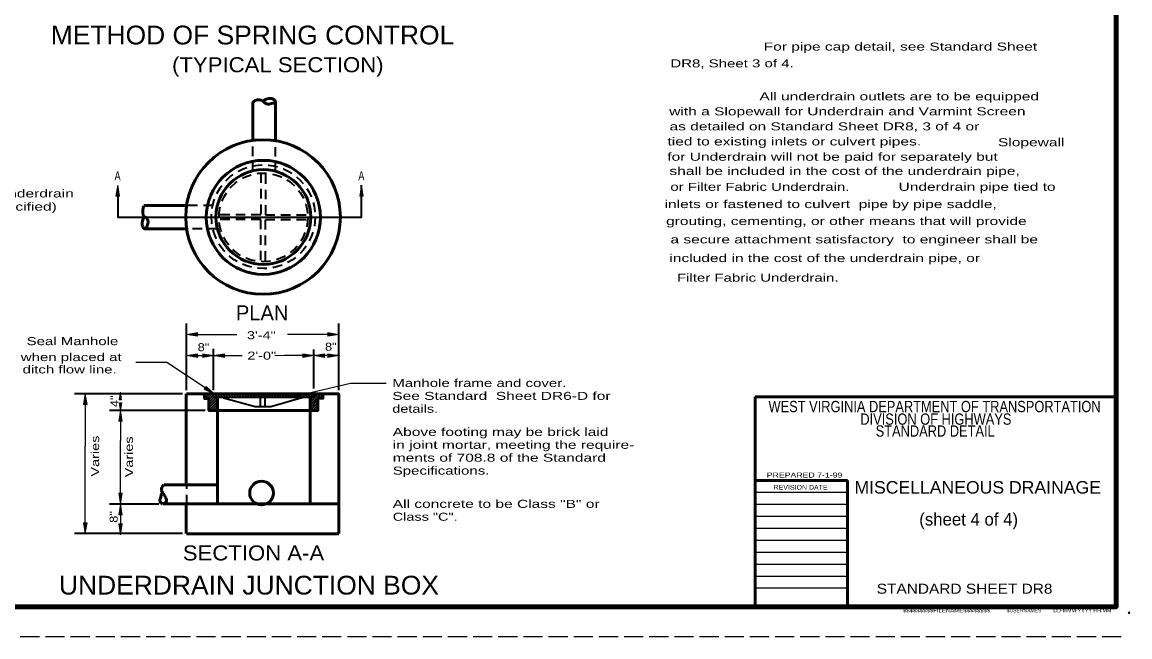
# Model space of a CAD drawing. Extents: x 36 to 71.3, y 0.3 to 22.3.
# Drawn here: x 52.91 to 71.32, y 0.32 to 10.54 of the extents above; entities that cross this region are included whole.
import ezdxf
from ezdxf.enums import TextEntityAlignment as Align

# ---------------------------------------------------------------- set-up
doc = ezdxf.new("R2010")
doc.units = 0
doc.header["$LTSCALE"] = 0.053
doc.header["$PDMODE"] = 32
doc.header["$PDSIZE"] = 0.0265
doc.linetypes.add('LONG_DASHED', pattern=[7.5, 6, -1.5])
doc.linetypes.add('MEDIUM_DASHED', pattern=[4.5, 3, -1.5])
for name, color, linetype, lineweight in [('1', 7, 'Continuous', 13), ('2', 7, 'Continuous', 13), ('3', 7, 'MEDIUM_DASHED', 53), ('4', 7, 'Continuous', 13)]:
    doc.layers.add(name, color=color, linetype=linetype, lineweight=lineweight)

msp = doc.modelspace()

# ---------------------------------------------------------------- hatches: boundary and pattern name
at = {"layer": '1'}
for points in [[(55.82417, 5.38142), (55.82417, 5.32142), (55.64417, 5.35142), (55.64417, 5.35142)], [(57.99158, 5.38142), (57.99158, 5.32142), (58.17158, 5.35142), (58.17158, 5.35142)], [(53.932, 4.18375), (53.992, 4.18375), (53.962, 4.36375), (53.962, 4.36375)], [(54.52358, 4.26292), (54.56558, 4.26292), (54.54458, 4.38892), (54.54458, 4.38892)], [(54.51642, 3.90858), (54.57642, 3.90858), (54.54642, 4.08858), (54.54642, 4.08858)], [(54.52542, 4.21458), (54.56733, 4.21458), (54.54642, 4.08858), (54.54642, 4.08858)], [(54.51642, 2.71217), (54.57642, 2.71217), (54.54642, 2.53217), (54.54642, 2.53217)], [(54.51642, 2.35217), (54.57642, 2.35217), (54.54642, 2.53217), (54.54642, 2.53217)], [(53.932, 2.22217), (53.992, 2.22217), (53.962, 2.04217), (53.962, 2.04217)], [(54.51642, 2.20217), (54.57642, 2.20217), (54.54642, 2.02225), (54.54642, 2.02225)]]:
    msp.add_hatch(color=256, dxfattribs=at).paths.add_polyline_path(points)
at = {"layer": '2'}
for points in [[(54.47033, 7.65), (54.53033, 7.65), (54.50033, 7.83), (54.50033, 7.83)], [(58.52092, 7.65), (58.58092, 7.65), (58.55092, 7.83), (58.55092, 7.83)], [(55.82417, 4.96867), (55.82417, 5.02867), (55.64417, 4.99867), (55.64417, 4.99867)], [(55.91408, 4.96867), (55.91408, 5.02867), (56.09408, 4.99867), (56.09408, 4.99867)], [(56.27417, 4.96867), (56.27417, 5.02867), (56.09408, 4.99867), (56.09408, 4.99867)], [(57.57775, 4.96867), (57.57775, 5.02867), (57.75775, 4.99867), (57.75775, 4.99867)], [(57.93775, 4.96867), (57.93775, 5.02867), (57.75775, 4.99867), (57.75775, 4.99867)], [(57.99158, 5.02867), (57.99158, 4.96867), (58.17158, 4.99867), (58.17158, 4.99867)], [(55.96925, 4.48833), (55.93608, 4.43833), (56.10258, 4.36375), (56.10258, 4.36375)], [(57.55025, 4.31875), (57.53642, 4.37708), (57.36817, 4.30642), (57.36817, 4.30642)]]:
    msp.add_hatch(color=256, dxfattribs=at).paths.add_polyline_path(points)

# ---------------------------------------------------------------- linework, layer by layer
at = {"layer": '1', "lineweight": 53}
for p, q in [((56.74692, 8.55658), (56.74692, 9.18117)), ((57.119, 8.55658), (57.119, 9.19325)), ((55.66483, 7.49225), (54.93608, 7.49225)), ((55.65717, 7.10817), (54.96808, 7.10817)), ((55.63758, 4.36375), (55.63758, 2.84675)), ((56.15717, 4.30325), (56.15717, 2.53683)), ((57.69492, 4.30325), (57.69492, 2.53683)), ((71.08992, 4.31392), (65.08992, 4.31392)), ((65.08992, 0.82408), (65.08992, 4.31392)), ((71.08992, 0.82408), (71.08992, 3.32308)), ((56.16042, 2.8515), (55.27317, 2.8515)), ((66.62783, 2.92308), (65.08992, 2.92308)), ((66.62783, 0.82408), (66.62783, 2.92308)), ((55.63533, 2.53683), (55.25342, 2.53683)), ((55.63758, 2.526), (55.63758, 2.04217)), ((55.64417, 2.53758), (58.17158, 2.53758)), ((65.08992, 2.23408), (65.08992, 0.82408)), ((55.64417, 2.0365), (58.17158, 2.0365)), ((71.08992, 0.82408), (65.08992, 0.82408))]:
    msp.add_line(p, q, dxfattribs=at)
at = {"layer": '1', "lineweight": 35}
for p, q in [((55.64417, 4.42625), (55.64417, 5.53142)), ((58.17158, 4.42625), (58.17158, 5.53142)), ((55.57508, 4.36375), (53.782, 4.36375)), ((55.9425, 4.32458), (55.98158, 4.36375)), ((55.9475, 4.2855), (56.02575, 4.36375)), ((55.99167, 4.2855), (56.07, 4.36375)), ((56.01625, 4.26583), (56.09108, 4.34067)), ((56.01625, 4.17742), (56.14525, 4.30642)), ((56.01625, 4.22158), (56.10108, 4.30642)), ((56.01625, 4.13325), (56.15717, 4.27408)), ((56.11417, 4.30642), (56.05692, 4.36375)), ((56.15833, 4.30642), (56.10108, 4.36375)), ((56.20258, 4.30642), (56.14525, 4.36375)), ((56.24675, 4.30642), (56.1895, 4.36375)), ((56.29092, 4.30642), (56.23367, 4.36375)), ((56.33517, 4.30642), (56.27783, 4.36375)), ((56.37933, 4.30642), (56.32208, 4.36375)), ((56.4235, 4.30642), (56.36625, 4.36375)), ((56.46775, 4.30642), (56.41042, 4.36375)), ((56.51192, 4.30642), (56.45467, 4.36375)), ((56.55608, 4.30642), (56.49883, 4.36375)), ((56.60033, 4.30642), (56.543, 4.36375)), ((56.6445, 4.30642), (56.58725, 4.36375)), ((56.68867, 4.30642), (56.63142, 4.36375)), ((56.73292, 4.30642), (56.67558, 4.36375)), ((56.77708, 4.30642), (56.71983, 4.36375)), ((56.82125, 4.30642), (56.764, 4.36375)), ((56.8655, 4.30642), (56.80817, 4.36375)), ((56.90967, 4.30642), (56.85242, 4.36375)), ((56.86825, 4.30642), (56.86825, 4.15392)), ((56.95383, 4.30642), (56.89658, 4.36375)), ((56.99808, 4.30642), (56.94075, 4.36375)), ((56.94533, 4.30642), (56.94533, 4.15392)), ((57.04225, 4.30642), (56.985, 4.36375)), ((57.08642, 4.30642), (57.02917, 4.36375)), ((57.13067, 4.30642), (57.07333, 4.36375)), ((57.17483, 4.30642), (57.11758, 4.36375)), ((57.219, 4.30642), (57.16175, 4.36375)), ((57.26325, 4.30642), (57.20592, 4.36375)), ((57.30742, 4.30642), (57.25017, 4.36375)), ((57.35158, 4.30642), (57.29433, 4.36375)), ((57.39583, 4.30642), (57.3385, 4.36375)), ((57.44, 4.30642), (57.38275, 4.36375)), ((57.48417, 4.30642), (57.42692, 4.36375)), ((57.52842, 4.30642), (57.47108, 4.36375)), ((57.57258, 4.30642), (57.51533, 4.36375)), ((57.61675, 4.30642), (57.5595, 4.36375)), ((57.661, 4.30642), (57.60367, 4.36375)), ((57.70517, 4.30642), (57.64792, 4.36375)), ((57.74933, 4.30642), (57.69208, 4.36375)), ((57.69492, 4.22092), (57.83775, 4.36375)), ((57.69492, 4.17675), (57.88192, 4.36375)), ((57.69492, 4.26517), (57.73625, 4.30642)), ((57.69492, 4.13258), (57.82592, 4.26358)), ((57.75658, 4.34342), (57.73625, 4.36375)), ((57.75658, 4.32675), (57.79358, 4.36375)), ((57.75658, 4.36133), (57.75658, 4.30642)), ((57.85267, 4.29033), (57.90958, 4.34717)), ((55.95375, 4.08858), (54.36642, 4.08858)), ((56.01625, 4.089), (56.15717, 4.22992)), ((56.06, 4.08858), (56.15717, 4.18575)), ((56.10417, 4.08858), (56.15717, 4.1415)), ((56.14833, 4.08858), (56.15717, 4.09733)), ((57.69517, 4.08858), (57.82592, 4.21933)), ((57.73933, 4.08858), (57.82592, 4.17517)), ((57.78358, 4.08858), (57.82592, 4.131)), ((55.18517, 2.53217), (54.36642, 2.53217)), ((55.57508, 2.04217), (53.782, 2.04217))]:
    msp.add_line(p, q, dxfattribs=at)
at = {"layer": '1', "lineweight": 25}
for p, q in [((55.82417, 5.35142), (56.47733, 5.35142)), ((57.99158, 5.35142), (57.32058, 5.35142)), ((53.962, 4.18375), (53.962, 3.49442)), ((54.54642, 3.90858), (54.54642, 3.58683)), ((54.54642, 2.71217), (54.54642, 3.58683)), ((53.962, 2.22217), (53.962, 3.49442)), ((66.62783, 2.72308), (65.08992, 2.72308)), ((66.62783, 2.52408), (65.08992, 2.52408)), ((54.54642, 2.35217), (54.54642, 2.06542)), ((66.62783, 2.32508), (65.08992, 2.32508)), ((66.62783, 2.12608), (65.08992, 2.12608)), ((66.62783, 1.92708), (65.08992, 1.92708)), ((66.62783, 1.72808), (65.08992, 1.72808)), ((66.62783, 1.52908), (65.08992, 1.52908)), ((66.62783, 1.33008), (65.08992, 1.33008)), ((66.62783, 1.13108), (65.08992, 1.13108))]:
    msp.add_line(p, q, dxfattribs=at)
at = {"layer": '1'}
msp.add_line((55.93742, 4.36375), (55.9425, 4.36883), dxfattribs=at)
at = {"layer": '1', "linetype": 'LONG_DASHED', "lineweight": 25}
msp.add_line((71.17325, 0.32408), (35.97325, 0.32408), dxfattribs=at)
at = {"layer": '1', "lineweight": 158}
msp.add_lwpolyline([(71.08992, 21.82408), (71.08992, 0.82408), (38.58992, 0.82408)], dxfattribs=at)
at = {"layer": '1'}
for points in [[(55.82417, 5.38142), (55.82417, 5.32142), (55.64417, 5.35142), (55.64417, 5.35142)], [(57.99158, 5.38142), (57.99158, 5.32142), (58.17158, 5.35142), (58.17158, 5.35142)], [(53.932, 4.18375), (53.992, 4.18375), (53.962, 4.36375), (53.962, 4.36375)], [(54.52358, 4.26292), (54.56558, 4.26292), (54.54458, 4.38892), (54.54458, 4.38892)], [(54.51642, 3.90858), (54.57642, 3.90858), (54.54642, 4.08858), (54.54642, 4.08858)], [(54.52542, 4.21458), (54.56733, 4.21458), (54.54642, 4.08858), (54.54642, 4.08858)], [(54.51642, 2.71217), (54.57642, 2.71217), (54.54642, 2.53217), (54.54642, 2.53217)], [(54.51642, 2.35217), (54.57642, 2.35217), (54.54642, 2.53217), (54.54642, 2.53217)], [(53.932, 2.22217), (53.992, 2.22217), (53.962, 2.04217), (53.962, 2.04217)], [(54.51642, 2.20217), (54.57642, 2.20217), (54.54642, 2.02225), (54.54642, 2.02225)]]:
    msp.add_lwpolyline(points, close=True, dxfattribs=at)
at = {"layer": '1', "lineweight": 53}
for points in [[(55.64417, 4.36375), (58.17158, 4.36375), (58.17158, 2.04217)], [(55.9425, 4.37342), (55.9425, 4.2855), (56.01625, 4.2855), (56.01625, 4.08858), (57.82592, 4.08858), (57.82592, 4.29033), (57.90958, 4.29033), (57.90958, 4.36375)]]:
    msp.add_lwpolyline(points, dxfattribs=at)
at = {"layer": '1', "lineweight": 35}
for points in [[(56.09108, 4.36133), (56.09108, 4.30642), (57.75658, 4.30642)], [(56.25508, 4.29917), (56.78242, 4.1515), (57.04433, 4.1515), (57.58375, 4.30642)]]:
    msp.add_lwpolyline(points, dxfattribs=at)
at = {"layer": '1', "lineweight": 53}
for centre, radius in [((56.91425, 7.30258), 1.28466), ((56.91975, 7.29692), 0.94816), ((56.91975, 7.30258), 0.78758), ((56.88975, 2.71475), 0.19625)]:
    msp.add_circle(centre, radius, dxfattribs=at)
for centre, radius, start, end in [((56.83833, 9.16983), 0.0961, 155.2019, 175.63882), ((56.79783, 9.1885), 0.05149, 127.0797, 155.12247), ((56.84, 9.133), 0.1212, 108.94125, 127.18911), ((56.83275, 9.15408), 0.09893, 88.71588, 108.94361), ((56.83058, 9.055), 0.19807, 76.71641, 88.71898), ((56.85317, 9.1515), 0.09893, 59.59849, 76.61699), ((56.8565, 9.15658), 0.09284, 40.84841, 59.78068), ((57.05033, 9.09525), 0.1881, 128.71883, 134.42111), ((56.99975, 9.28008), 0.09628, 220.69947, 239.29641), ((56.98325, 9.1785), 0.08118, 119.88486, 128.57223), ((57.02867, 9.10025), 0.17164, 109.56978, 120.00186), ((57.07258, 8.9765), 0.30301, 101.70708, 109.55079), ((57.03217, 9.17083), 0.10452, 78.59323, 101.63549), ((57.03208, 9.16967), 0.10561, 55.75148, 78.65852), ((57.042, 9.18442), 0.08784, 22.54048, 55.73033), ((57.11183, 9.21333), 0.01232, 283.06396, 22.6714), ((57.06933, 9.39767), 0.23291, 239.34105, 250.23371), ((57.00117, 9.208), 0.03134, 250.28519, 280.2853), ((56.95392, 9.46933), 0.29692, 280.25658, 284.97067), ((57.29667, 8.18033), 1.03686, 102.34271, 104.8682), ((57.21133, 8.58275), 0.62555, 100.5317, 102.58856), ((57.026, 9.591), 0.39957, 280.23196, 282.80535), ((55.21508, 7.39042), 0.29891, 176.13604, 181.98558), ((55.0645, 7.385), 0.14822, 181.89394, 194.28181), ((55.27492, 7.38525), 0.35896, 170.60889, 175.95477), ((54.99908, 7.43108), 0.07936, 159.14959, 170.75763), ((55.13867, 7.37817), 0.22868, 152.37523, 159.20126), ((55.11692, 7.19258), 0.21035, 167.07021, 180.02724), ((55.03525, 7.19242), 0.12864, 179.95854, 196.55623), ((55.0305, 7.21258), 0.12168, 152.26599, 167.11937), ((55.05458, 7.38258), 0.13805, 194.32618, 207.14842), ((55.07525, 7.1885), 0.17248, 139.65423, 152.11683), ((54.965, 7.33658), 0.03732, 207.04975, 256.06413), ((54.9445, 7.25392), 0.04778, 33.03592, 76.11025), ((54.87017, 7.20558), 0.13645, 17.24885, 33.0313), ((54.69125, 7.26042), 0.31741, 341.51299, 347.83317), ((54.91667, 7.22017), 0.08775, 357.45357, 17.19024), ((54.86783, 7.22167), 0.13658, 348.08645, 357.71518), ((55.01433, 7.18625), 0.10683, 196.60859, 225.50325), ((54.95108, 7.12192), 0.01661, 225.54926, 303.97956), ((54.93158, 7.15092), 0.05155, 303.90889, 328.26467), ((54.82983, 7.214), 0.17124, 328.23759, 341.53955), ((55.29917, 2.78058), 0.07228, 180.71653, 196.81167), ((55.25942, 2.77992), 0.0325, 159.37068, 180.37997), ((55.45808, 2.70558), 0.24457, 151.8833, 159.4729), ((55.32058, 2.779), 0.08869, 140.44668, 151.87321), ((55.36125, 2.74533), 0.14151, 131.39497, 140.42378), ((55.27517, 2.59658), 0.07298, 167.92759, 186.3476), ((55.30333, 2.5995), 0.10124, 186.23364, 201.83885), ((55.57975, 2.53167), 0.38439, 164.84735, 167.96588), ((56.41083, 2.30275), 1.24643, 162.94519, 164.6764), ((55.49742, 2.5835), 0.29083, 158.05889, 163.04008), ((55.79175, 2.46517), 0.60806, 154.63246, 158.07888), ((55.3475, 2.7945), 0.12256, 196.49946, 208.85168), ((55.9205, 3.11183), 0.77753, 208.95904, 211.83559), ((54.514, 2.2395), 0.8775, 29.07679, 31.78423), ((53.69842, 1.78542), 1.81096, 27.99799, 29.0905), ((54.7955, 2.36767), 0.56898, 26.14012, 28.09179), ((55.19792, 2.63442), 0.12405, 324.17729, 334.27041), ((55.263, 2.59742), 0.04803, 10.53744, 25.86089), ((55.291, 2.58967), 0.02073, 334.07049, 358.89637), ((55.22783, 2.59033), 0.08394, 359.26131, 10.87301), ((55.24367, 2.57567), 0.03705, 201.92052, 238.47981), ((55.25, 2.58583), 0.04896, 238.42067, 270.12984), ((55.25, 2.59617), 0.05935, 270.08059, 297.24403), ((55.24933, 2.59725), 0.06062, 297.36206, 324.24479)]:
    msp.add_arc(centre, radius, start, end, dxfattribs=at)
at = {"layer": '1'}
for p in [(71.08992, 0.82408), (71.30292, 0.72408)]:
    msp.add_point(p, dxfattribs=at)
at = {"layer": '2'}
for p, q in [((58.55092, 7.65), (58.55092, 7.35833)), ((57.11267, 4.99867), (58.17158, 4.99867))]:
    msp.add_line(p, q, dxfattribs=at)
at = {"layer": '2', "lineweight": 25}
for p, q in [((55.82417, 4.99867), (56.56558, 4.99867)), ((58.17158, 4.99867), (57.27158, 4.99867))]:
    msp.add_line(p, q, dxfattribs=at)
at = {"layer": '2', "lineweight": 35}
for p, q in [((56.09417, 4.42275), (56.09417, 5.10942)), ((57.75775, 4.4505), (57.75775, 5.1005))]:
    msp.add_line(p, q, dxfattribs=at)
at = {"layer": '2'}
for points in [[(54.47033, 7.65), (54.53033, 7.65), (54.50033, 7.83), (54.50033, 7.83)], [(58.52092, 7.65), (58.58092, 7.65), (58.55092, 7.83), (58.55092, 7.83)], [(55.82417, 4.96867), (55.82417, 5.02867), (55.64417, 4.99867), (55.64417, 4.99867)], [(55.91408, 4.96867), (55.91408, 5.02867), (56.09408, 4.99867), (56.09408, 4.99867)], [(56.27417, 4.96867), (56.27417, 5.02867), (56.09408, 4.99867), (56.09408, 4.99867)], [(57.57775, 4.96867), (57.57775, 5.02867), (57.75775, 4.99867), (57.75775, 4.99867)], [(57.93775, 4.96867), (57.93775, 5.02867), (57.75775, 4.99867), (57.75775, 4.99867)], [(57.99158, 5.02867), (57.99158, 4.96867), (58.17158, 4.99867), (58.17158, 4.99867)], [(55.96925, 4.48833), (55.93608, 4.43833), (56.10258, 4.36375), (56.10258, 4.36375)], [(57.55025, 4.31875), (57.53642, 4.37708), (57.36817, 4.30642), (57.36817, 4.30642)]]:
    msp.add_lwpolyline(points, close=True, dxfattribs=at)
at = {"layer": '2', "lineweight": 35}
msp.add_lwpolyline([(54.50033, 7.65), (54.50033, 7.30292), (58.55092, 7.30292), (58.55092, 7.83)], dxfattribs=at)
at = {"layer": '2', "lineweight": 25}
for points in [[(55.95267, 4.46333), (55.315, 4.88708), (54.80117, 4.88708)], [(57.54333, 4.34792), (58.3685, 4.54333), (58.96233, 4.54333)]]:
    msp.add_lwpolyline(points, dxfattribs=at)
at = {"layer": '2'}
msp.add_point((58.17158, 4.99867), dxfattribs=at)
at = {"layer": '3', "lineweight": 35}
for p, q in [((56.74692, 8.05633), (56.74692, 8.55658)), ((57.119, 8.04825), (57.119, 8.55658)), ((56.08208, 7.49225), (55.66483, 7.49225)), ((56.16133, 7.10817), (55.65717, 7.10817)), ((55.64742, 2.526), (55.64742, 2.84675))]:
    msp.add_line(p, q, dxfattribs=at)
for points in [[(56.879, 8.02808), (56.879, 7.33733), (56.19433, 7.33733)], [(56.95392, 8.01592), (56.95392, 7.33733), (57.65617, 7.33733)], [(56.879, 6.58358), (56.879, 7.26308), (56.18225, 7.26308)], [(56.95392, 6.578), (56.95392, 7.26308), (57.65067, 7.26308)]]:
    msp.add_lwpolyline(points, dxfattribs=at)
for centre, radius in [((56.91975, 7.30825), 0.86262), ((56.91975, 7.29692), 0.73674)]:
    msp.add_circle(centre, radius, dxfattribs=at)
at = {"layer": '4'}
for p, q in [((55.64417, 5.35142), (55.64425, 5.35142)), ((55.63758, 4.36375), (55.63767, 4.36375)), ((55.64417, 4.36375), (55.64425, 4.36375)), ((58.17158, 4.36375), (58.17167, 4.36375)), ((56.01625, 4.08858), (56.01633, 4.08858)), ((54.54642, 2.53217), (54.5465, 2.53217)), ((55.24767, 2.53217), (55.24775, 2.53217)), ((53.962, 2.04217), (53.96208, 2.04217)), ((55.63758, 2.04217), (55.63767, 2.04217))]:
    msp.add_line(p, q, dxfattribs=at)

# ---------------------------------------------------------------- texts
at = {"layer": '1'}
for s, height, width, p in [('For pipe cap detail, see Standard Sheet', 0.133, 1.45, (65.23267, 10.06958)), ('DR8, Sheet 3 of 4.', 0.133, 1.4, (63.68258, 9.79058)), ('All underdrain outlets are to be equipped', 0.133, 1.45, (65.16217, 9.24192)), ('with a Slopewall for Underdrain and Varmint Screen ', 0.133, 1.45, (63.663, 8.99367)), ('as detailed on Standard Sheet DR8, 3 of 4 or ', 0.133, 1.45, (63.66817, 8.743)), ('tied to existing inlets or culvert pipes.', 0.133, 1.45, (63.634, 8.49233)), ('Slopewall ', 0.133, 1.45, (69.12492, 8.47933)), ('for Underdrain will not be paid for separately but', 0.133, 1.45, (63.6315, 8.23825)), ('shall be included in the cost of the underdrain pipe,', 0.133, 1.45, (63.66692, 8.00175)), ('or Filter Fabric Underdrain.', 0.133, 1.4, (63.68183, 7.73808)), ('Underdrain pipe tied to ', 0.133, 1.45, (67.47342, 7.73875)), (' inlets or fastened to culvert  pipe by pipe saddle,', 0.133, 1.45, (63.5145, 7.45117)), (' grouting, cementing, or other means that will provide', 0.133, 1.45, (63.539, 7.16933)), ('a secure attachment satisfactory  to engineer shall be', 0.133, 1.45, (63.68325, 6.86425)), (' included in the cost of the underdrain pipe, or', 0.133, 1.45, (63.594, 6.55383)), ('Filter Fabric Underdrain.', 0.133, 1.4, (63.79225, 6.22833)), ('3\'-4"', 0.133, 1.35, (56.64742, 5.272)), ('REVISION DATE', 0.079, 1.1, (65.397, 2.77042)), ('$$$$$$$$$FILENAME$$$$$$$$', 0.06, 1.25, (67.54567, 0.73233)), ('$USERNAME$', 0.06, 1.05, (69.26975, 0.73233)), ('DD-MMM-YYYY HH:MM', 0.06, 1.1, (70.04333, 0.73233))]:
    msp.add_text(s, height=height, dxfattribs=dict(at, width=width)).set_placement(p)
for s, height, width, p in [('WEST VIRGINIA DEPARTMENT OF TRANSPORTATION', 0.1875, 0.85, (68.07167, 4.059)), ('DIVISION OF HIGHWAYS', 0.1875, 0.85, (68.09354, 3.85008)), ('STANDARD DETAIL', 0.1875, 0.85, (68.08225, 3.65192)), (' PREPARED 7-1-99', 0.08333, 1.3, (65.89113, 2.97225)), (' MISCELLANEOUS DRAINAGE ', 0.2083, 1.05, (68.78825, 2.70508)), ('STANDARD SHEET DR8       ', 0.1667, 1.15, (68.82004, 1.04117))]:
    msp.add_text(s, height=height, dxfattribs=dict(at, width=width)).set_placement(p, align=Align.CENTER)
at = {"layer": '1', "width": 1.35}
for p in [(54.19133, 2.98875), (54.75233, 2.97583)]:
    msp.add_text('Varies', height=0.133, rotation=90, dxfattribs=at).set_placement(p)
at = {"layer": '1'}
msp.add_text('     (sheet 4 of 4)     ', height=0.2083, dxfattribs=at).set_placement((68.63804, 2.17425), align=Align.CENTER)
at = {"layer": '2'}
for s, height, width, p in [('METHOD OF SPRING CONTROL', 0.3125, 1.05, (53.38792, 10.172)), ('(TYPICAL SECTION)', 0.25, 1.1, (55.403, 9.70917)), ('A', 0.15, 0.75, (54.44758, 7.91375)), ('A', 0.15, 0.75, (58.49825, 7.91375)), (' Non-Perforated Underdrain', 0.133, 1.45, (50.58817, 7.62842)), ('Pipe (4" or as Specified)', 0.133, 1.45, (50.71592, 7.40958)), ('Seal Manhole', 0.133, 1.4, (52.98725, 5.173)), ('8"', 0.133, 1.2, (55.82775, 5.07283)), ('8"', 0.133, 1.2, (57.94417, 5.08175)), ('when placed at', 0.133, 1.4, (52.88983, 4.908)), ('2\'-0"', 0.133, 1.35, (56.6545, 4.93275)), ('ditch flow line.', 0.133, 1.4, (52.91867, 4.70292)), ('Manhole frame and cover.', 0.133, 1.4, (59.06208, 4.4775)), ('See Standard  Sheet DR6-D for', 0.133, 1.45, (59.06208, 4.26325)), ('details.', 0.133, 1.35, (59.06208, 4.04892)), ('Above footing may be brick laid', 0.133, 1.45, (59.06983, 3.66408)), ('in joint mortar, meeting the require-', 0.133, 1.45, (59.06983, 3.44983)), ('ments of 708.8 of the Standard', 0.133, 1.45, (59.06983, 3.23558)), ('Specifications.', 0.133, 1.4, (59.06983, 3.02125)), ('All concrete to be Class "B" or', 0.133, 1.45, (59.06983, 2.46817)), ('Class "C".', 0.133, 1.35, (59.06983, 2.25383)), ('SECTION A-A', 0.25, 1.1, (55.58142, 1.59392)), ('UNDERDRAIN JUNCTION BOX', 0.3125, 1.05, (53.52375, 1.02717))]:
    msp.add_text(s, height=height, dxfattribs=dict(at, width=width)).set_placement(p)
msp.add_text('PLAN', height=0.25, dxfattribs=at).set_placement((56.46292, 5.58533))
at = {"layer": '2', "width": 1.2}
for s, p in [('4"', (54.51242, 4.14383)), ('8"', (54.49892, 2.21942))]:
    msp.add_text(s, height=0.133, rotation=90, dxfattribs=at).set_placement(p)

doc.saveas('drawing.dxf')
